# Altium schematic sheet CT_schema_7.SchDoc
size 278 x 170 mm
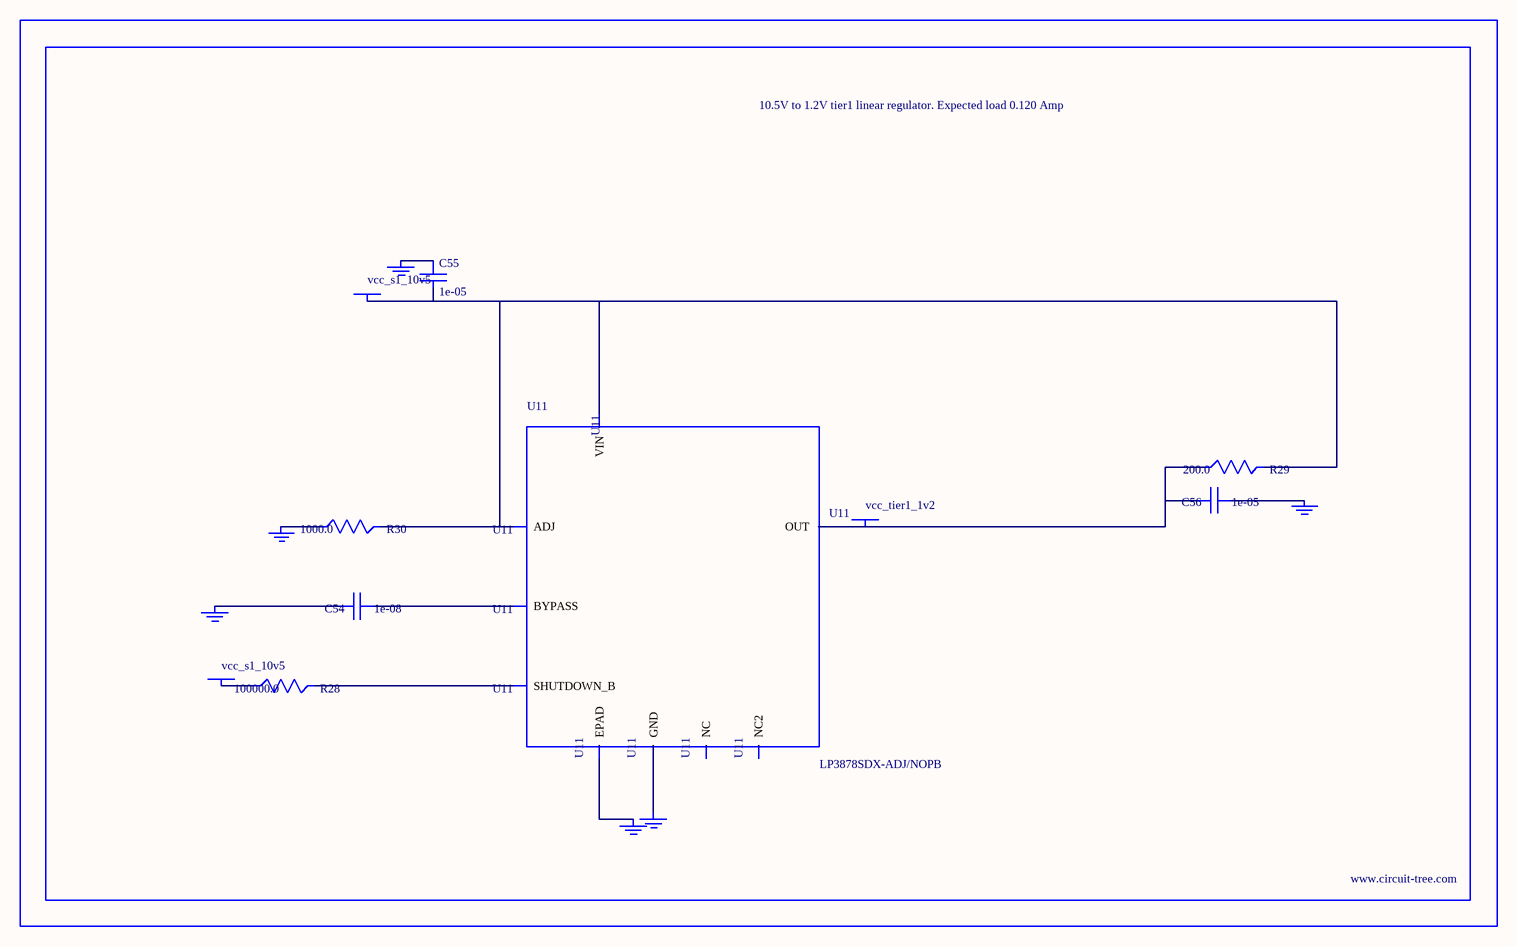
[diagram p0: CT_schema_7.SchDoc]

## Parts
BORDER6  (no value)
C54  1e-08  [C0402]
C55  1e-05  [C1206]
C56  1e-05  [C0805]
GND_INSTANCE_6_0  (no value)
GND_INSTANCE_6_1  (no value)
GND_INSTANCE_6_2  (no value)
GND_INSTANCE_6_3  (no value)
GND_INSTANCE_6_4  (no value)
GND_INSTANCE_6_5  (no value)
POWER_INSTANCE_6_0  vcc_s1_10v5
POWER_INSTANCE_6_1  vcc_s1_10v5
POWER_INSTANCE_6_2  vcc_tier1_1v2
R28  100000.0  [R0603]
R29  200.0  [R0603]
R30  1000.0  [R0603]
U11  LP3878SDX-ADJ/NOPB  [WSON-8]

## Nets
NetC54_1: C54.1 U11.1(BYPASS)
NetC54_2: C54.2 GND_INSTANCE_6_0.0(GND)
NetC55_1: C55.1 GND_INSTANCE_6_1.0(GND)
NetC55_2: C55.2 POWER_INSTANCE_6_0.0(PWR) R29.2 R30.2 U11.4(VIN) U11.6(ADJ)
NetC56_1: C56.1 GND_INSTANCE_6_2.0(GND)
NetC56_2: C56.2 POWER_INSTANCE_6_2.0(PWR) R29.1 U11.5(OUT)
NetGND_INSTANCE_6_3_0: GND_INSTANCE_6_3.0(GND) R30.1
NetGND_INSTANCE_6_4_0: GND_INSTANCE_6_4.0(GND) U11.PAD(EPAD)
NetGND_INSTANCE_6_5_0: GND_INSTANCE_6_5.0(GND) U11.3(GND)
NetPOWER_INSTANCE_6_1_0: POWER_INSTANCE_6_1.0(PWR) R28.1
NetR28_2: R28.2 U11.8(SHUTDOWN_B)

Not connected (* = marked no-connect by the designer): U11 2(NC) 7(NC2)

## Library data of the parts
BORDER6 = BORDER_PAGE6
C54 = C0402C103K3RAC
C55 = C1206C106K3RACTU
C56 = GRM219R60J106ME19D
GND_INSTANCE_6_0-GND_INSTANCE_6_5 = GND
POWER_INSTANCE_6_0-POWER_INSTANCE_6_2 = PWR
R28 = RC0603JR-07100KL
R29 = RC0603JR-07200RL
R30 = RC0603JR-071KL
